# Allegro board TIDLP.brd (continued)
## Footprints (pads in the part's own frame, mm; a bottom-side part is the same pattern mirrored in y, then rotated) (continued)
CAP-FK-V-CASEE_PAN
  rect 1.422x4.166 smd: 1(0,-2.857) 2(0,2.857)
CAP_0402
  rect 0.508x0.508 smd: 1(-0.521,0) 2(0.521,0)
CAP_0603
  rect 1.067x1.016 smd: 1(-0.864,0) 2(0.864,0)
CAP_0805
  rect 1.27x1.524 smd: 1(-0.965,0) 2(0.965,0)
CAP_1206
  rect 1.575x1.626 smd: 1(-1.714,0) 2(1.714,0)
CAP_1210
  rect 1.575x2.591 smd: 1(-1.397,0) 2(1.397,0)
CN3_53398_MOLEX
  rect 2.108x2.997 smd: (-3.8,-1.85) (3.8,-1.85)
  rect 0.61x1.6 smd: 1(-1.25,1.063) 2(0,1.063) 3(1.25,1.063)
CN120_QTH_SAMTEC
  round 0.762 hole 1.016 unplated: (-19.24,2.03) (19.24,2.03)
  rect 0.305x1.448 smd: 1(-17.25,3.08) 2(-17.25,-3.09) 3(-16.75,3.08) 4(-16.75,-3.09) 5(-16.25,3.08) 6(-16.25,-3.09) 7(-15.75,3.08) 8(-15.75,-3.09) 9(-15.25,3.08) 10(-15.25,-3.09) 11(-14.75,3.08) 12(-14.75,-3.09) 13(-14.25,3.08) 14(-14.25,-3.09) 15(-13.75,3.08) 16(-13.75,-3.09) 17(-13.25,3.08) 18(-13.25,-3.09) 19(-12.75,3.08) 20(-12.75,-3.09) 21(-12.25,3.08) 22(-12.25,-3.09) 23(-11.75,3.08) 24(-11.75,-3.09) 25(-11.25,3.08) 26(-11.25,-3.09) 27(-10.75,3.08) 28(-10.75,-3.09) 29(-10.25,3.08) 30(-10.25,-3.09) 31(-9.75,3.08) 32(-9.75,-3.09) 33(-9.25,3.08) 34(-9.25,-3.09) 35(-8.75,3.08) 36(-8.75,-3.09) 37(-8.25,3.08) 38(-8.25,-3.09) 39(-7.75,3.08) 40(-7.75,-3.09) 41(-7.25,3.08) 42(-7.25,-3.09) 43(-6.75,3.08) 44(-6.75,-3.09) 45(-6.25,3.08) 46(-6.25,-3.09) 47(-5.75,3.08) 48(-5.75,-3.09) 49(-5.25,3.08) 50(-5.25,-3.09) 51(-4.75,3.08) 52(-4.75,-3.09) 53(-4.25,3.08) 54(-4.25,-3.09) 55(-3.75,3.08) 56(-3.75,-3.09) 57(-3.25,3.08) 58(-3.25,-3.09) 59(-2.75,3.08) 60(-2.75,-3.09) 61(2.75,3.08) 62(2.75,-3.09) 63(3.25,3.08) 64(3.25,-3.09) 65(3.75,3.08) 66(3.75,-3.09) 67(4.25,3.08) 68(4.25,-3.09) 69(4.75,3.08) 70(4.75,-3.09) 71(5.25,3.08) 72(5.25,-3.09) 73(5.75,3.08) 74(5.75,-3.09) 75(6.25,3.08) 76(6.25,-3.09) 77(6.75,3.08) 78(6.75,-3.09) 79(7.25,3.08) 80(7.25,-3.09) 81(7.75,3.08) 82(7.75,-3.09) 83(8.25,3.08) 84(8.25,-3.09) 85(8.75,3.08) 86(8.75,-3.09) 87(9.25,3.08) 88(9.25,-3.09) 89(9.75,3.08) 90(9.75,-3.09) 91(10.25,3.08) 92(10.25,-3.09) 93(10.75,3.08) 94(10.75,-3.09) 95(11.25,3.08) 96(11.25,-3.09) 97(11.75,3.08) 98(11.75,-3.09) 99(12.25,3.08) 100(12.25,-3.09) 101(12.75,3.08) 102(12.75,-3.09) 103(13.25,3.08) 104(13.25,-3.09) 105(13.75,3.08) 106(13.75,-3.09) 107(14.25,3.08) 108(14.25,-3.09) 109(14.75,3.08) 110(14.75,-3.09) 111(15.25,3.08) 112(15.25,-3.09) 113(15.75,3.08) 114(15.75,-3.09) 115(16.25,3.08) 116(16.25,-3.09) 117(16.75,3.08) 118(16.75,-3.09) 119(17.25,3.08) 120(17.25,-3.09)
  rect 2.54x0.635 smd: G1(-18.445,0) G4(-1.555,0) G5(1.555,0) G8(18.445,0)
  rect 4.699x0.635 smd: G2(-13.175,0) G3(-6.825,0) G6(6.825,0) G7(13.175,0)
CN150CUSTOM_REV
  round 1.27 hole 1.676 unplated: (-6.096,-1.397) (36.576,-1.397)
  round 1.27 hole 4.623 unplated: (-3.81,3.175) (34.29,3.175)
  round 0.762 smd: 1A(0,0) 1B(0,1.27) 1C(0,2.54) 1D(0,3.81) 1E(0,5.08) 1F(0,6.35) 2A(1.27,0) 2B(1.27,1.27) 2C(1.27,2.54) 2D(1.27,3.81) 2E(1.27,5.08) 2F(1.27,6.35) 3A(2.54,0) 3B(2.54,1.27) 3C(2.54,2.54) 3D(2.54,3.81) 3E(2.54,5.08) 3F(2.54,6.35) 4A(3.81,0) 4B(3.81,1.27) 4C(3.81,2.54) 4D(3.81,3.81) 4E(3.81,5.08) 4F(3.81,6.35) 5A(5.08,0) 5B(5.08,1.27) 5C(5.08,2.54) 5D(5.08,3.81) 5E(5.08,5.08) 5F(5.08,6.35) 6A(6.35,0) 6B(6.35,1.27) 6C(6.35,2.54) 6D(6.35,3.81) 6E(6.35,5.08) 6F(6.35,6.35) 7A(7.62,0) 7B(7.62,1.27) 7C(7.62,2.54) 7D(7.62,3.81) 7E(7.62,5.08) 7F(7.62,6.35) 8A(8.89,0) 8B(8.89,1.27) 8C(8.89,2.54) 8D(8.89,3.81) 8E(8.89,5.08) 8F(8.89,6.35) 9A(10.16,0) 9B(10.16,1.27) 9C(10.16,2.54) 9D(10.16,3.81) 9E(10.16,5.08) 9F(10.16,6.35) 10A(11.43,0) 10B(11.43,1.27) 10C(11.43,2.54) 10D(11.43,3.81) 10E(11.43,5.08) 10F(11.43,6.35) 11A(12.7,0) 11B(12.7,1.27) 11C(12.7,2.54) 11D(12.7,3.81) 11E(12.7,5.08) 11F(12.7,6.35) 12A(13.97,0) 12B(13.97,1.27) 12C(13.97,2.54) 12D(13.97,3.81) 12E(13.97,5.08) 12F(13.97,6.35) 13A(15.24,0) 13B(15.24,1.27) 13C(15.24,2.54) 13D(15.24,3.81) 13E(15.24,5.08) 13F(15.24,6.35) 14A(16.51,0) 14B(16.51,1.27) 14C(16.51,2.54) 14D(16.51,3.81) 14E(16.51,5.08) 14F(16.51,6.35) 15A(17.78,0) 15B(17.78,1.27) 15C(17.78,2.54) 15D(17.78,3.81) 15E(17.78,5.08) 15F(17.78,6.35) 16A(19.05,0) 16B(19.05,1.27) 16C(19.05,2.54) 16D(19.05,3.81) 16E(19.05,5.08) 16F(19.05,6.35) 17A(20.32,0) 17B(20.32,1.27) 17C(20.32,2.54) 17D(20.32,3.81) 17E(20.32,5.08) 17F(20.32,6.35) 18A(21.59,0) 18B(21.59,1.27) 18C(21.59,2.54) 18D(21.59,3.81) 18E(21.59,5.08) 18F(21.59,6.35) 19A(22.86,0) 19B(22.86,1.27) 19C(22.86,2.54) 19D(22.86,3.81) 19E(22.86,5.08) 19F(22.86,6.35) 20A(24.13,0) 20B(24.13,1.27) 20C(24.13,2.54) 20D(24.13,3.81) 20E(24.13,5.08) 20F(24.13,6.35) 21A(25.4,0) 21B(25.4,1.27) 21C(25.4,2.54) 21D(25.4,3.81) 21E(25.4,5.08) 21F(25.4,6.35) 22A(26.67,0) 22B(26.67,1.27) 22C(26.67,2.54) 22D(26.67,3.81) 22E(26.67,5.08) 22F(26.67,6.35) 23A(27.94,0) 23B(27.94,1.27) 23C(27.94,2.54) 23D(27.94,3.81) 23E(27.94,5.08) 23F(27.94,6.35) 24A(29.21,0) 24B(29.21,1.27) 24C(29.21,2.54) 24D(29.21,3.81) 24E(29.21,5.08) 24F(29.21,6.35) 25A(30.48,0) 25B(30.48,1.27) 25C(30.48,2.54) 25D(30.48,3.81) 25E(30.48,5.08) 25F(30.48,6.35)
CONN4-52808_MOLEX
  rect 0.61x1.448 smd: 1(-1.501,-1.778) 3(0.5,-1.778)
  rect 0.61x1.651 smd: 2(-0.5,1.778) 4(1.501,1.778)
CONN4-53398_MOLEX
  rect 0.61x1.6 smd: 1(-1.875,0) 2(-0.625,0) 3(0.625,0) 4(1.875,0)
  rect 2.108x2.997 smd: 5(-4.425,-2.913) 6(4.425,-2.913)
CONN4-67068-1000_MOLEX
  round 1.422 hole 0.914: 1(0,0) 2(-2.5,0) 3(-2.5,-2) 4(0,-2)
  round 3.175 hole 2.286: S1(-7.27,-4.71) S2(4.77,-4.71)
CONN5-53398-0590_MOLEX
  rect 0.61x1.6 smd: 1(-2.5,1.063) 2(-1.25,1.063) 3(0,1.063) 4(1.25,1.063) 5(2.5,1.063)
  rect 2.108x2.997 smd: 6(-5.05,-1.85) 7(5.05,-1.85)
CONN6-53398-0690_MOLEX
  rect 0.61x1.6 smd: 1(-3.125,1.063) 2(-1.875,1.063) 3(-0.625,1.063) 4(0.625,1.063) 5(1.875,1.063) 6(3.125,1.063)
  rect 2.108x2.997 smd: 7(-5.675,-1.85) 8(5.675,-1.85)
CONN8-43045-0813_MOLEX
  round 1.524 hole 1.016: (-11.989,3.937) (2.997,3.937) 1(0,0) 2(-2.997,0) 3(-5.994,0) 4(-8.992,0) 5(0,2.997) 6(-2.997,2.997) 7(-5.994,2.997) 8(-8.992,2.997)
CONN10-SQT_SAM
  rect 1.778x1.778 hole 1.27: 1(0,0)
  round 1.778 hole 1.27: 2(0,-1.999) 3(0,-3.998) 4(0,-5.997) 5(0,-7.996) 6(0,-9.995) 7(0,-11.994) 8(0,-13.993) 9(0,-15.992) 10(0,-17.991)
CONN12-53398_MOLEX
  rect 2.108x2.997 smd: (-9.425,-1.85) (9.425,-1.85)
  rect 0.61x1.6 smd: 1(-6.875,1.063) 2(-5.625,1.063) 3(-4.375,1.063) 4(-3.125,1.063) 5(-1.875,1.063) 6(-0.625,1.063) 7(0.625,1.063) 8(1.875,1.063) 9(3.125,1.063) 10(4.375,1.063) 11(5.625,1.063) 12(6.875,1.063)
CONN12-FH12_HRS
  rect 1.854x2.184 smd: (-4.5,-2.895) (4.5,-2.895)
  rect 0.254x1.016 smd: 1(-2.75,0) 2(-2.25,0) 3(-1.75,0) 4(-1.25,0) 5(-0.75,0) 6(-0.25,0) 7(0.25,0) 8(0.75,0) 9(1.25,0) 10(1.75,0) 11(2.25,0) 12(2.75,0)
CONN12-SMT-TSM-112-SV_SAMTEC
  rect 3.175x1.27 smd: 1(-1.587,-13.97) 2(1.587,-11.43) 3(-1.587,-8.89) 4(1.587,-6.35) 5(-1.587,-3.81) 6(1.587,-1.27) 7(-1.587,1.27) 8(1.587,3.81) 9(-1.587,6.35) 10(1.587,8.89) 11(-1.587,11.43) 12(1.587,13.97)
CONN14-53048_MLX
  rect 1.016x1.016 hole 0.508: 1(0,0)
  round 1.016 hole 0.508: 2(0,-1.25) 3(0,-2.5) 4(0,-3.75) 5(0,-5) 6(0,-6.25) 7(0,-7.5) 8(0,-8.75) 9(0,-10) 10(0,-11.25) 11(0,-12.5) 12(0,-13.75) 13(0,-15) 14(0,-16.25)
CONN14-XF2M_OMRON
  rect 0.254x1.295 smd: 1(3.25,0) 2(2.75,0) 3(2.25,0) 4(1.75,0) 5(1.25,0) 6(0.75,0) 7(0.25,0) 8(-0.25,0) 9(-0.75,0) 10(-1.25,0) 11(-1.75,0) 12(-2.25,0) 13(-2.75,0) 14(-3.25,0)
  rect 1.905x1.524 smd: 15(-5.201,-3.987) 16(5.201,-3.987)
CONN20-TSM-110-0X-X-DV-A_SAMTEC
  round 1.016 hole 1.88 unplated: (-10.16,0) (10.16,0)
  rect 1.27x3.175 smd: 1(-11.43,-2.731) 2(-11.43,2.731) 3(-8.89,-2.731) 4(-8.89,2.731) 5(-6.35,-2.731) 6(-6.35,2.731) 7(-3.81,-2.731) 8(-3.81,2.731) 9(-1.27,-2.731) 10(-1.27,2.731) 11(1.27,-2.731) 12(1.27,2.731) 13(3.81,-2.731) 14(3.81,2.731) 15(6.35,-2.731) 16(6.35,2.731) 17(8.89,-2.731) 18(8.89,2.731) 19(11.43,-2.731) 20(11.43,2.731)
CONN22-B22B-PHD_JST
  rect 1.473x1.473 hole 0.965: 1(0,0)
  round 1.473 hole 0.965: 2(2,0) 3(0,2) 4(2,2) 5(0,4) 6(2,4) 7(0,6) 8(2,6) 9(0,8) 10(2,8) 11(0,10) 12(2,10) 13(0,12) 14(2,12) 15(0,14) 16(2,14) 17(0,16) 18(2,16) 19(0,18) 20(2,18) 21(0,20) 22(2,20)
CRY4-P73_ECS
  rect 1.397x2.007 smd: 1(-2.54,-2.095) 2(2.54,-2.095) 3(2.54,2.095) 4(-2.54,2.095)
DIO-SMA
  rect 2.489x1.702 smd: 1(-2.007,0) 2(2.007,0)
DIO-SMB
  rect 2.4x2.4 smd: 1(-2.2,0) 2(2.2,0)
DIO_SMA
  rect 2.489x1.702 smd: 1(-2.007,0) 2(2.007,0)
FLTR_0603
  rect 1.067x1.016 smd: 1(-0.864,0) 2(0.864,0)
HDR1X3-TMM1030X-X-S_SAM
  rect 1.524x1.524 hole 1.016: 1(0,0)
  round 1.524 hole 1.016: 2(2,0) 3(4,0)
HDR2_2MM
  rect 1.651x1.651 hole 1.143: 1(0,0)
  round 1.651 hole 1.143: 2(2,0)
HDR10X2-5103308_TYCO
  round 1.651 hole 1.067: 1(0,0) 2(2.54,0) 3(0,-2.54) 4(2.54,-2.54) 5(0,-5.08) 6(2.54,-5.08) 7(0,-7.62) 8(2.54,-7.62) 9(0,-10.16) 10(2.54,-10.16) 11(0,-12.7) 12(2.54,-12.7) 13(0,-15.24) 14(2.54,-15.24) 15(0,-17.78) 16(2.54,-17.78) 17(0,-20.32) 18(2.54,-20.32) 19(0,-22.86) 20(2.54,-22.86)
HDR14-87227_AMP
  rect 1.473x1.473 hole 0.965: 1(0,0)
  round 1.473 hole 0.965: 2(0,2.54) 3(2.54,0) 4(2.54,2.54) 5(5.08,0) 6(5.08,2.54) 7(7.62,0) 8(7.62,2.54) 9(10.16,0) 10(10.16,2.54) 11(12.7,0) 12(12.7,2.54) 13(15.24,0) 14(15.24,2.54)
IND2-SPR7030_BOU
  rect 2.413x2.489 smd: 1(-3.054,0) 2(3.054,0)
IND_0805
  rect 1.27x1.524 smd: 1(-0.965,0) 2(0.965,0)
IND_SERH
  rect 1.702x3.81 smd: 1(-2.85,0) 2(2.85,0)
IND_SRR1005
  rect 2.997x2.794 smd: 1(5.144,0) 2(-5.144,0)
JACK3-DCPOWER_CUI_MOD
  round 1.524 hole 1.016: (0,1.25) (0,1) (0,0.75) (0,0.5) (0,0.25) (0,-0.25) (0,-0.5) (0,-0.75) (0,-1) (0,-1.25) (2,4.7) (2.25,4.7) (2.5,4.7) (2.75,4.7) (3.25,4.7) (3.5,4.7) (3.75,4.7) (4,4.7) (6,1) (6,0.75) (6,0.5) (6,0.25) (6,-0.25) (6,-0.5) (6,-0.75) (6,-1) GND1(3,4.7) GND2(6,0) P12V_IN(0,0)
KYCON-CN9SMTA
  round 3.81 hole 3.048: (-12.495,-0.325) (12.495,-0.325)
  round 0.762 hole 1.524 unplated: (-8.99,-0.325) (8.99,-0.325)
  rect 0.8x3.7 smd: 1(-5.54,0.325) 2(-2.77,0.325) 3(0,0.325) 4(2.77,0.325) 5(5.54,0.325) 6(-4.155,0.325) 7(-1.385,0.325) 8(1.385,0.325) 9(4.155,0.325)
LCC8-MXD2125_MEMSIC
  round 0.508 smd: (0,0.648)
  rect 2.032x0.864 smd: 1(-2.235,1.27) 2(-2.235,0) 3(-2.235,-1.27) 5(2.235,-1.27) 6(2.235,0) 7(2.235,1.27)
  rect 0.864x2.032 smd: 4(0,-2.235) 8(0,2.235)
LED_S_TYPE
  rect 0.787x1.092 smd: 1(-1.25,0.65)
  rect 0.787x0.889 smd: 2(1.25,0.65) 3(-1.25,-0.65) 4(1.25,-0.65)
MH276-157GND
  round 7.01 hole 3.988: 1(0,0)
  round 0.813 hole 0.406: 2(0,3.048) 3(-2.159,2.159) 4(-3.048,0) 5(-2.159,-2.159) 6(0,-3.048) 7(2.159,-2.159) 8(3.048,0) 9(2.159,2.159)
MICTOR_HPA
  round 1.27 hole 2.388 unplated: (11.43,0)
  rect 0.432x1.27 smd: 1(5.715,3.531) 2(5.715,-3.531) 3(5.08,3.531) 4(5.08,-3.531) 5(4.445,3.531) 6(4.445,-3.531) 7(3.81,3.531) 8(3.81,-3.531) 9(3.175,3.531) 10(3.175,-3.531) 11(2.54,3.531) 12(2.54,-3.531) 13(1.905,3.531) 14(1.905,-3.531) 15(1.27,3.531) 16(1.27,-3.531) 17(0.635,3.531) 18(0.635,-3.531) 19(0,3.531) 20(0,-3.531) 21(-0.635,3.531) 22(-0.635,-3.531) 23(-1.27,3.531) 24(-1.27,-3.531) 25(-1.905,3.531) 26(-1.905,-3.531) 27(-2.54,3.531) 28(-2.54,-3.531) 29(-3.175,3.531) 30(-3.175,-3.531) 31(-3.81,3.531) 32(-3.81,-3.531) 33(-4.445,3.531) 34(-4.445,-3.531) 35(-5.08,3.531) 36(-5.08,-3.531) 37(-5.715,3.531) 38(-5.715,-3.531)
  round 1.397 hole 0.889: G1(-5.08,0) G2(-2.54,0) G3(0,0) G4(2.54,0) G5(5.08,0)
POT-3314G
  rect 1.321x1.321 smd: 1(-1.156,2.756) 3(1.156,2.756)
  rect 1.981x1.321 smd: 2(0,-2.756)
PQFP24-QFN_SI
  oval 1.016x0.305 smd: 1(-2,1.25) 6(-2,-1.25) 13(2,-1.25) 18(2,1.25)
  rect 1.016x0.305 smd: 2(-2,0.75) 3(-2,0.25) 4(-2,-0.25) 5(-2,-0.75) 14(2,-0.75) 15(2,-0.25) 16(2,0.25) 17(2,0.75)
  oval 0.305x1.016 smd: 7(-1.25,-2) 12(1.25,-2) 19(1.25,2) 24(-1.25,2)
  rect 0.305x1.016 smd: 8(-0.75,-2) 9(-0.25,-2) 10(0.25,-2) 11(0.75,-2) 20(0.75,2) 21(0.25,2) 22(-0.25,2) 23(-0.75,2)
  round 0.61 hole 0.305: 25(0,0) PAD(-0.889,0.889)
PQFP100-PZ_TI
  rect 1.524x0.254 smd: 1(-7.762,6) 2(-7.762,5.5) 3(-7.762,5) 4(-7.762,4.5) 5(-7.762,4) 6(-7.762,3.5) 7(-7.762,3) 8(-7.762,2.5) 9(-7.762,2) 10(-7.762,1.5) 11(-7.762,1) 12(-7.762,0.5) 13(-7.762,0) 14(-7.762,-0.5) 15(-7.762,-1) 16(-7.762,-1.5) 17(-7.762,-2) 18(-7.762,-2.5) 19(-7.762,-3) 20(-7.762,-3.5) 21(-7.762,-4) 22(-7.762,-4.5) 23(-7.762,-5) 24(-7.762,-5.5) 25(-7.762,-6) 51(7.762,-6) 52(7.762,-5.5) 53(7.762,-5) 54(7.762,-4.5) 55(7.762,-4) 56(7.762,-3.5) 57(7.762,-3) 58(7.762,-2.5) 59(7.762,-2) 60(7.762,-1.5) 61(7.762,-1) 62(7.762,-0.5) 63(7.762,0) 64(7.762,0.5) 65(7.762,1) 66(7.762,1.5) 67(7.762,2) 68(7.762,2.5) 69(7.762,3) 70(7.762,3.5) 71(7.762,4) 72(7.762,4.5) 73(7.762,5) 74(7.762,5.5) 75(7.762,6)
  rect 0.254x1.524 smd: 26(-6,-7.762) 27(-5.5,-7.762) 28(-5,-7.762) 29(-4.5,-7.762) 30(-4,-7.762) 31(-3.5,-7.762) 32(-3,-7.762) 33(-2.5,-7.762) 34(-2,-7.762) 35(-1.5,-7.762) 36(-1,-7.762) 37(-0.5,-7.762) 38(0,-7.762) 39(0.5,-7.762) 40(1,-7.762) 41(1.5,-7.762) 42(2,-7.762) 43(2.5,-7.762) 44(3,-7.762) 45(3.5,-7.762) 46(4,-7.762) 47(4.5,-7.762) 48(5,-7.762) 49(5.5,-7.762) 50(6,-7.762) 76(6,7.762) 77(5.5,7.762) 78(5,7.762) 79(4.5,7.762) 80(4,7.762) 81(3.5,7.762) 82(3,7.762) 83(2.5,7.762) 84(2,7.762) 85(1.5,7.762) 86(1,7.762) 87(0.5,7.762) 88(0,7.762) 89(-0.5,7.762) 90(-1,7.762) 91(-1.5,7.762) 92(-2,7.762) 93(-2.5,7.762) 94(-3,7.762) 95(-3.5,7.762) 96(-4,7.762) 97(-4.5,7.762) 98(-5,7.762) 99(-5.5,7.762) 100(-6,7.762)
QF48_PPAD
  rect 1.524x0.254 smd: 1(-4.445,2.752) 2(-4.445,2.252) 3(-4.445,1.751) 4(-4.445,1.251) 5(-4.445,0.751) 6(-4.445,0.25) 7(-4.445,-0.25) 8(-4.445,-0.751) 9(-4.445,-1.251) 10(-4.445,-1.751) 11(-4.445,-2.252) 12(-4.445,-2.752) 25(4.445,-2.752) 26(4.445,-2.252) 27(4.445,-1.751) 28(4.445,-1.251) 29(4.445,-0.751) 30(4.445,-0.25) 31(4.445,0.25) 32(4.445,0.751) 33(4.445,1.251) 34(4.445,1.751) 35(4.445,2.252) 36(4.445,2.752)
  rect 0.254x1.524 smd: 13(-2.752,-4.445) 14(-2.252,-4.445) 15(-1.751,-4.445) 16(-1.251,-4.445) 17(-0.751,-4.445) 18(-0.25,-4.445) 19(0.25,-4.445) 20(0.751,-4.445) 21(1.251,-4.445) 22(1.751,-4.445) 23(2.252,-4.445) 24(2.752,-4.445) 37(2.752,4.445) 38(2.252,4.445) 39(1.751,4.445) 40(1.251,4.445) 41(0.751,4.445) 42(0.25,4.445) 43(-0.25,4.445) 44(-0.751,4.445) 45(-1.251,4.445) 46(-1.751,4.445) 47(-2.252,4.445) 48(-2.752,4.445)
RES_0402
  rect 0.508x0.508 smd: 1(-0.521,0) 2(0.521,0)
RES_0603
  rect 1.067x1.016 smd: 1(-0.864,0) 2(0.864,0)
RES_0805
  rect 1.27x1.524 smd: 1(-0.965,0) 2(0.965,0)
RES_1206
  rect 1.575x1.626 smd: 1(-1.714,0) 2(1.714,0)
RES_1210
  rect 1.575x2.591 smd: 1(-1.397,0) 2(1.397,0)
RES_2010
  rect 1.778x2.591 smd: 1(-2.21,0) 2(2.21,0)
RNET8-EXB38V_PAN
  rect 0.94x0.787 smd: 1(-0.8,1.314) 4(-0.8,-1.314) 5(0.8,-1.314) 8(0.8,1.314)
  rect 0.94x0.559 smd: 2(-0.8,0.4) 3(-0.8,-0.4) 6(0.8,-0.4) 7(0.8,0.4)
RNET16-EXB-2HV_PAN
  rect 0.686x0.305 smd: 1(-0.851,1.75) 2(-0.851,1.25) 3(-0.851,0.75) 4(-0.851,0.25) 5(-0.851,-0.25) 6(-0.851,-0.75) 7(-0.851,-1.25) 8(-0.851,-1.75) 9(0.851,-1.75) 10(0.851,-1.25) 11(0.851,-0.75) 12(0.851,-0.25) 13(0.851,0.25) 14(0.851,0.75) 15(0.851,1.25) 16(0.851,1.75)
SM_TO_252_DPAK
  rect 1.6x2.997 smd: 1(-2.286,-4.318) 2(0,-4.318) 3(2.286,-4.318)
  rect 6.198x5.791 smd: 4(0,2.642)
SMC_ST
  rect 2.794x3.81 smd: 1(-3.569,0) 2(3.569,0)
SMD_49
  rect 5.486x2.007 smd: 1(-4.75,0) 2(4.75,0)
SOD-123
  rect 1.016x1.27 smd: 1(-1.778,0) 2(1.778,0)
SOIC5-DBV_TI
  rect 1.321x0.61 smd: 1(-1.187,0.95) 2(-1.187,0) 3(-1.187,-0.95) 4(1.187,-0.95) 5(1.187,0.95)
SOIC6-DBV_TI
  rect 1.321x0.61 smd: 1(-1.187,0.95) 2(-1.187,0) 3(-1.187,-0.95) 4(1.187,-0.95) 5(1.187,0) 6(1.187,0.95)
SOIC6-DRL_TI
  rect 0.356x1.067 smd: 1(-0.5,-0.828) 2(0,-0.828) 3(0.5,-0.828) 4(0.5,0.828) 5(0,0.828) 6(-0.5,0.828)
SOIC8-D_TI
  rect 0.635x2.032 smd: 1(-1.905,-2.489) 2(-0.635,-2.489) 3(0.635,-2.489) 4(1.905,-2.489) 5(1.905,2.489) 6(0.635,2.489) 7(-0.635,2.489) 8(-1.905,2.489)
SOIC8-PW_TI
  rect 0.356x1.524 smd: 1(-0.975,-2.96) 2(-0.325,-2.96) 3(0.325,-2.96) 4(0.975,-2.96) 5(0.975,2.96) 6(0.325,2.96) 7(-0.325,2.96) 8(-0.975,2.96)
SOIC14-PW_TI
  rect 0.305x1.778 smd: 1(-1.951,-2.794) 2(-1.301,-2.794) 3(-0.65,-2.794) 4(0,-2.794) 5(0.65,-2.794) 6(1.301,-2.794) 7(1.951,-2.794) 8(1.951,2.794) 9(1.301,2.794) 10(0.65,2.794) 11(0,2.794) 12(-0.65,2.794) 13(-1.301,2.794) 14(-1.951,2.794)
SOIC16-PW_TI
  rect 0.356x1.524 smd: 1(-2.275,-2.96) 2(-1.625,-2.96) 3(-0.975,-2.96) 4(-0.325,-2.96) 5(0.325,-2.96) 6(0.975,-2.96) 7(1.625,-2.96) 8(2.275,-2.96) 9(2.275,2.96) 10(1.625,2.96) 11(0.975,2.96) 12(0.325,2.96) 13(-0.325,2.96) 14(-0.975,2.96) 15(-1.625,2.96) 16(-2.275,2.96)
SOIC24-PW_TI
  rect 0.356x1.524 smd: 1(-3.575,-2.96) 2(-2.925,-2.96) 3(-2.275,-2.96) 4(-1.625,-2.96) 5(-0.975,-2.96) 6(-0.325,-2.96) 7(0.325,-2.96) 8(0.975,-2.96) 9(1.625,-2.96) 10(2.275,-2.96) 11(2.925,-2.96) 12(3.575,-2.96) 13(3.575,2.96) 14(2.925,2.96) 15(2.275,2.96) 16(1.625,2.96) 17(0.975,2.96) 18(0.325,2.96) 19(-0.325,2.96) 20(-0.975,2.96) 21(-1.625,2.96) 22(-2.275,2.96) 23(-2.925,2.96) 24(-3.575,2.96)
SOIC56-DGG_TI
  rect 0.305x1.524 smd: 1(-6.75,-3.775) 2(-6.25,-3.775) 3(-5.75,-3.775) 4(-5.25,-3.775) 5(-4.75,-3.775) 6(-4.25,-3.775) 7(-3.75,-3.775) 8(-3.25,-3.775) 9(-2.75,-3.775) 10(-2.25,-3.775) 11(-1.75,-3.775) 12(-1.25,-3.775) 13(-0.75,-3.775) 14(-0.25,-3.775) 15(0.25,-3.775) 16(0.75,-3.775) 17(1.25,-3.775) 18(1.75,-3.775) 19(2.25,-3.775) 20(2.75,-3.775) 21(3.25,-3.775) 22(3.75,-3.775) 23(4.25,-3.775) 24(4.75,-3.775) 25(5.25,-3.775) 26(5.75,-3.775) 27(6.25,-3.775) 28(6.75,-3.775) 29(6.75,3.775) 30(6.25,3.775) 31(5.75,3.775) 32(5.25,3.775) 33(4.75,3.775) 34(4.25,3.775) 35(3.75,3.775) 36(3.25,3.775) 37(2.75,3.775) 38(2.25,3.775) 39(1.75,3.775) 40(1.25,3.775) 41(0.75,3.775) 42(0.25,3.775) 43(-0.25,3.775) 44(-0.75,3.775) 45(-1.25,3.775) 46(-1.75,3.775) 47(-2.25,3.775) 48(-2.75,3.775) 49(-3.25,3.775) 50(-3.75,3.775) 51(-4.25,3.775) 52(-4.75,3.775) 53(-5.25,3.775) 54(-5.75,3.775) 55(-6.25,3.775) 56(-6.75,3.775)
SOT23-3_FC
  rect 1.016x1.372 smd: 1(0.94,1.092) 2(-0.94,1.092) 3(0,-1.092)
SOT23-DBV_TI
  rect 0.508x1.372 smd: 1(-0.94,-1.219) 2(0,-1.219) 3(0.94,-1.219) 4(0.94,1.219) 5(-0.94,1.219)
SOT23AVXC
  rect 1.016x1.372 smd: 1(0,-1.092) 2(-0.94,1.092) 3(0.94,1.092)
SOT23AVXD
  rect 1.016x1.372 smd: 1(-0.94,1.092) 2(0.94,1.092) 3(0,-1.092)
SOT223
  rect 1.499x2.007 smd: 1(-2.299,-3.15) 2(0,-3.15) 3(2.299,-3.15)
  rect 3.81x2.007 smd: 4(0,3.15)
SOT_323
  rect 0.762x1.067 smd: 1(0.66,0.94) 2(-0.66,0.94) 3(0,-0.94)
SSOP_8
  rect 0.305x1.6 smd: 1(-0.975,-2.235) 2(-0.325,-2.235) 3(0.325,-2.235) 4(0.975,-2.235) 5(0.975,2.136) 6(0.325,2.136) 7(-0.325,2.136) 8(-0.975,2.136)
SW_GT12
  rect 3.175x0.762 smd: (-2.603,2.54) (-2.603,-2.54) (2.603,0) 1(2.603,2.54) 3(2.603,-2.54)
TP
  round 1.219 hole 0.711: 1(0,0)
TSOP_56_48_DUAL_SKT
  round 1.27 hole 1.27 unplated: (-5.08,4.743) (5.08,4.743)
  rect 1.778x0.305 smd: 1(-9.69,6.75) 2(-9.69,6.25) 3(-9.69,5.75) 4(-9.69,5.25) 5(-9.69,4.75) 6(-9.69,4.25) 7(-9.69,3.75) 8(-9.69,3.25) 9(-9.69,2.75) 10(-9.69,2.25) 11(-9.69,1.75) 12(-9.69,1.25) 13(-9.69,0.75) 14(-9.69,0.25) 15(-9.69,-0.25) 16(-9.69,-0.75) 17(-9.69,-1.25) 18(-9.69,-1.75) 19(-9.69,-2.25) 20(-9.69,-2.75) 21(-9.69,-3.25) 22(-9.69,-3.75) 23(-9.69,-4.25) 24(-9.69,-4.75) 25(-9.69,-5.25) 26(-9.69,-5.75) 27(-9.69,-6.25) 28(-9.69,-6.75) 29(9.69,-6.75) 30(9.69,-6.25) 31(9.69,-5.75) 32(9.69,-5.25) 33(9.69,-4.75) 34(9.69,-4.25) 35(9.69,-3.75) 36(9.69,-3.25) 37(9.69,-2.75) 38(9.69,-2.25) 39(9.69,-1.75) 40(9.69,-1.25) 41(9.69,-0.75) 42(9.69,-0.25) 43(9.69,0.25) 44(9.69,0.75) 45(9.69,1.25) 46(9.69,1.75) 47(9.69,2.25) 48(9.69,2.75) 49(9.69,3.25) 50(9.69,3.75) 51(9.69,4.25) 52(9.69,4.75) 53(9.69,5.25) 54(9.69,5.75) 55(9.69,6.25) 56(9.69,6.75)
TSOPII_44
  rect 0.61x1.143 smd: 1(-8.4,-6) 2(-7.6,-6) 3(-6.8,-6) 4(-6,-6) 5(-5.2,-6) 6(-4.4,-6) 7(-3.6,-6) 8(-2.8,-6) 9(-2,-6) 10(-1.2,-6) 11(-0.4,-6) 12(0.4,-6) 13(1.2,-6) 14(2,-6) 15(2.8,-6) 16(3.6,-6) 17(4.4,-6) 18(5.2,-6) 19(6,-6) 20(6.8,-6) 21(7.6,-6) 22(8.4,-6) 23(8.4,6) 24(7.6,6) 25(6.8,6) 26(6,6) 27(5.2,6) 28(4.4,6) 29(3.6,6) 30(2.8,6) 31(2,6) 32(1.2,6) 33(0.4,6) 34(-0.4,6) 35(-1.2,6) 36(-2,6) 37(-2.8,6) 38(-3.6,6) 39(-4.4,6) 40(-5.2,6) 41(-6,6) 42(-6.8,6) 43(-7.6,6) 44(-8.4,6)
TSSOP_8
  rect 0.406x1.803 smd: 1(-0.975,-2.954) 2(-0.325,-2.954) 3(0.325,-2.954) 4(0.975,-2.954) 5(0.975,2.954) 6(0.325,2.954) 7(-0.325,2.954) 8(-0.975,2.954)
TSSOP_14
  rect 0.305x1.778 smd: 1(-1.951,-2.794) 2(-1.301,-2.794) 3(-0.65,-2.794) 4(0,-2.794) 5(0.65,-2.794) 6(1.301,-2.794) 7(1.951,-2.794) 8(1.951,2.794) 9(1.301,2.794) 10(0.65,2.794) 11(0,2.794) 12(-0.65,2.794) 13(-1.301,2.794) 14(-1.951,2.794)
unnamed#2
  round 0.762 smd: 1(0,0)
unnamed#3
  round 2.362 hole 2.349 unplated: (-20.955,20.955) (-20.955,-20.955) (20.955,20.955) (20.955,-20.955)
  round 0.635 hole 0.66 unplated: (-18.989,-18.989) (18.989,18.989)
VISHAY_IR_TSOP348
  rect 1.575x1.575 hole 1.067: 1(0,0)
  round 1.575 hole 1.067: 2(2.54,0) 3(5.08,0)

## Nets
AGND: C539.2 C558.2 C559.2 C560.2 C561.2 C562.2 C563.2 C564.2 C565.2 C573.2 C574.2 C575.2 J11.2 J11.5 R571.2 R572.2 R583.2 R585.2 R586.1 R598.2 U7.13 U7.14 U7.25 U7.39
GND: C1.1 C2.2 C3.2 C4.2 C5.2 C7.2 C8.2 C9.2 C10.2 C11.2 C12.2 C13.2 C14.2 C15.2 C16.2 C17.1 C18.2 C19.2 C20.2 C21.2 C22.1 C23.1 C25.1 C26.1 C27.1 C28.1 C29.1 C30.1 C31.1 C33.1 C34.1 C35.1 C36.1 C37.1 C503.1 C504.1 C506.1 C508.1 C509.1 C511.1 C512.1 C513.2 C514.2 C516.1 C517.1 C518.1 C519.1 C520.1 C521.2 C522.2 C523.1 C524.2 C525.2 C526.1 C527.1 C529.1 C530.2 C531.2 C532.2 C533.2 C534.2 C535.2 C536.2 C537.2 C538.2 C540.2 C541.1 C543.2 C544.2 C545.1 C546.2 C547.2 C548.2 C549.2 C550.2 C551.1 C552.2 C553.2 C554.2 C555.2 C556.2 C557.2 C566.2 C567.1 C568.2 C569.2 C570.2 C571.2 C572.2 C578.2 C579.1 C583.1 C584.2 C585.2 C586.2 C587.2 C588.2 C589.2 C590.2 C591.2 C592.2 C593.2 C594.2 C595.2 C596.2 C597.2 C598.2 C599.2 C600.2 C601.2 C602.2 C603.2 C604.2 C605.2 C606.1 C607.1 C608.2 C609.2 C610.2 C611.2 C612.2 C613.2 C614.2 C615.2 C616.2 C617.2 C618.2 C619.2 C620.2 C621.2 C622.2 C623.2 C624.2 C625.2 C626.2 C627.2 C628.2 C629.2 C630.2 C631.2 C632.2 C633.2 C634.2 C635.1 C636.1 C637.1 C638.2 C639.1 C640.2 C643.1 C644.1 C645.2 C646.2 C647.2 C648.2 C649.2 C650.2 C651.2 C652.2 C653.2 C654.2 C655.2 C656.2 C657.2 C658.2 C659.2 C660.2 C661.2 C662.1 C663.1 C664.2 C665.1 C666.1 C668.2 C669.2 C670.2 C671.2 C672.2 C673.1 C674.1 C676.1 C677.1 C678.1 C679.1 C680.1 C681.1 C682.1 C683.1 C684.1 C685.1 C686.1 C687.1 C688.1 C689.1 C690.1 C691.1 C692.1 C693.1 C694.1 C695.1 C696.1 C697.1 C698.1 C699.1 C700.1 C701.1 C702.1 C703.1 C704.1 C705.1 C706.1 C707.1 C708.1 C709.1 D1.2 D2.2 D3.2 D4.2 D6.2 D7.2 D8.2 D9.1 D10.1 D501.1 D502.2 D503.2 D504.2 D505.2 D506.2 D507.2 D508.2 DN500.1 DN501.1 DN502.1 DN503.1 DN505.1 DN506.1 DN507.1 DN508.1 J1.4 J1.8 J1.10 J1.12 J2.G1 J2.G2 J2.G3 J2.G4 J2.G5 J2.G6 J2.G7 J2.G8 J3.G1 J3.G2 J3.G3 J3.G4 J3.G5 J3.G6 J3.G7 J3.G8 J5.4 J6.2 J7.2 J8.3 J9.6 J10.5 J17.2 J20.5 J21.5 J22.5 J23.7 J23.10 J23.15 J23.16 J24.1 J24.20 J25.2 J27.GND1 J27.GND2 J28.4 J28.6 J28.8 J28.10 J28.12 J28.14 J28.16 J28.18 J28.20 J29.4 J30.3 J31.3 J32.5 J32.G1 J32.G2 J32.G3 J32.G4 J32.G5 J33.9 J33.10 J33.11 J33.12 J35.3 J37.1 J37.3 J37.5 J37.7 J38.1 J39.5 J40.13 J40.14 J41.4 J42.3 J43.3 J44.3 J47.6 J48.2 J49.6 J50.2 J52.9 J52.10 J52.14 J53.2 J54.4 J55.4 J56.4 J57.3 J58.3 J59.3 J59.5 J59.7 J59.9 J59.11 J60.3 J62.3 J64.3 J65.3 J66.3 J67.3 J500.1A J500.1D J500.2C J500.2F J500.3A J500.3D J500.4C J500.4F J500.5A J500.5D J500.6C J500.6F J500.7A J500.7D J500.8C J500.8F J500.9A J500.9D J500.10C J500.10F J500.11A J500.11D J500.12C J500.12F J500.13D J500.14C J500.14F J500.15A J500.15D J500.16C J500.16F J500.17A J500.17D J500.18C J500.18F J500.19A J500.19D J500.20C J500.20F J500.21A J500.21D J500.22C J500.22F J500.23A J500.23D J500.24C J500.24F J500.25A J500.25D MT1.1 MT2.1 MT3.1 MT4.1 MT5.1 MT6.1 Q3.1 Q4.1 Q501.1 Q502.1 Q503.1 Q504.1 Q507.1 R5.2 R23.2 R34.2 R52.2 R510.1 R518.2 R520.2 R521.1 R524.1 R537.1 R542.1 R569.2 R571.1 R574.2 R585.1 R597.2 R598.1 R600.1 R640.1 R650.1 R664.1 R669.2 R670.1 R679.1 R681.1 R683.1 R688.2 R698.2 R703.2 R705.2 R710.1 R734.1 R755.2 R757.2 R769.1 R773.1 R788.1 R789.1 R790.1 R791.1 R792.1 R793.1 RN1.5 RN1.6 RN1.7 RN1.8 RN500.5 RN500.6 RN500.7 RN500.8 RN501.5 RN501.6 RN501.7 RN501.8 RN502.5 RN502.6 RN502.7 RN502.8 RN503.5 RN504.5 RN504.6 RN504.7 RN504.8 TP44.1 U1.2 U2.7 U2.19 U2.44 U3.3 U3.7 U4.8 U4.19 U4.38 U4.49 U5.2 U5.3 U6.15 U7.2 U7.11 U7.35 U7.41 U7.49 U7.55 U7.62 U7.69 U7.77 U7.87 U7.88 U7.89 U7.94 U8.1 U8.12 U8.13 U9.4 U10.4 U11.A1 U11.A2 U11.A3 U11.A17 U11.A18 U11.A24 U11.A25 U11.A26 U11.AA6 U11.AA9 U11.AA12 U11.AA15 U11.AA18 U11.AA21 U11.AB5 U11.AB14 U11.AB15 U11.AB16 U11.AB17 U11.AB22 U11.AC4 U11.AC6 U11.AC17 U11.AC18 U11.AC23 U11.AD3 U11.AD17 U11.AD18 U11.AD24 U11.AE3 U11.AE17 U11.AE24 U11.AE25 U11.AF1 U11.AF2 U11.AF3 U11.AF17 U11.AF24 U11.AF25 U11.AF26 U11.B1 U11.B2 U11.B3 U11.B17 U11.B18 U11.B25 U11.C3 U11.C18 U11.C24 U11.D4 U11.D17 U11.D18 U11.D23 U11.E5 U11.E15 U11.E16 U11.E17 U11.E22 U11.F6 U11.F9 U11.F12 U11.F15 U11.F18 U11.F21 U11.G5 U11.J5 U11.J6 U11.J21 U11.K5 U11.K26 U11.L5 U11.L12 U11.L13 U11.L14 U11.L15 U11.L23 U11.L25 U11.M6 U11.M11 U11.M12 U11.M13 U11.M14 U11.M15 U11.M16 U11.M21 U11.M22 U11.M25 U11.N5 U11.N11 U11.N12 U11.N13 U11.N14 U11.N15 U11.N16 U11.P11 U11.P12 U11.P13 U11.P14 U11.P15 U11.P16 U11.P24 U11.R5 U11.R6 U11.R11 U11.R12 U11.R13 U11.R14 U11.R15 U11.R16 U11.R24 U11.R26 U11.T12 U11.T13 U11.T14 U11.T15 U11.U5 U11.V5 U11.V6 U11.V21 U11.W5 U11.Y5 U12.15 U13.12 U13.34 U14.1 U14.33 U14.52 U14.56 U15.7 U15.19 U15.44 U16.4 U16.7 U18.3 U19.2 U20.19 U20.25 U21.2 U500.3 U501.8 U501.10 U502.2 U503.2 U503.5 U504.3 U505.7 U506.1 U506.2 U506.3 U506.4 U506.5 U506.11 U506.12 U506.13 U507.3 U508.14 U509.3 U510.8 U510.10 U510.11 U511.1 U511.3 U512.2 U512.8 U512.10 U513.1 U513.3 U514.1 U514.2 U515.4 U516.2 U516.3 U517.1 U517.12 U517.13 U518.8 U518.15 U519.1 U519.12 U519.13 U520.3 U521.4 U522.1 U522.3 U523.1 U523.3 U524.1 U524.3 U525.3 U526.1 U526.3 VR1.1 VR2.1
P5V: C3.1 C5.1 C684.2 C705.2 J2.9 J2.11 J3.9 J3.11 J20.8 J30.1 J58.1 J59.1 Q506.2 R19.1 R641.1 R713.2 R758.2 R775.1 R786.1 TP33.1
P5V_CONN: J37.4 R713.1
P5V_IR: C506.2 R508.1 U1.3
P5V_IR_CONN: C37.2 R66.1 U21.3
P12V: C18.1 C19.1 C505.2 C512.2 C519.2 C520.2 C527.2 C564.1 C638.1 C639.2 C641.2 C664.1 C665.2 C666.2 C672.1 C706.2 DN500.2 DN501.2 DN502.2 DN503.2 DN505.2 DN506.2 DN507.2 DN508.2 FB504.2 J23.2 J36.2 J39.1 J40.1 J40.2 J57.1 J500.15F J500.16A J500.16B Q5.2 Q5.4 R1.1 R11.2 R15.2 R634.2 R706.1 R714.1 R716.1 R730.2 R731.2 R732.2 R759.2 R760.2 R761.2 TP51.1 U2.9 U2.22 U2.23 U2.27 U2.37 U2.42 U2.43 U15.9 U15.22 U15.27 U15.37 U15.42 U505.2
P12V_FIL: C29.2 C32.1 FB8.2 J36.1 Q5.3 R37.2 R39.1 R40.1 TP53.1
P12V_IN: C28.2 FB8.1 J27.P12V_IN J37.6
VDD1_INDEX_SENSE: C703.2 J62.1 R780.1
VDD2_INDEX_SENSE: C704.2 J60.1 R781.1
VDD_TILT: C508.2 R512.1 U3.8
3D_TOGGLE: U11.E26 U519.8 U522.2
A1P8V: R527.1 R620.1
A1P8V_SENSE: C23.2 C642.2 R620.2 R633.1 R639.2 TP40.1 U15.29
A_BLU_PWM: J23.5 J24.7 U8.21
A_GRN_PWM: J23.3 J24.5 U8.22
A_LED4_PWM: J23.9 J24.2 U8.20
A_LED5_PWM: J23.11 J24.4 U8.19
A_LED6_PWM: J23.13 J24.6 U8.18
A_LED7_PWM: J23.17 J24.11 U8.17
A_LED8_PWM: J23.19 J24.13 U8.16
A_RED_PWM: J23.1 J24.3 U8.23
A_SPARE_1: J23.18 J38.2 U519.23
A_SPARE_2: J23.22 U8.15
A_SPARE_3: J23.20 U8.14
A_SSP0_CLK: R27.2 R28.2 TP56.1 U11.AD4
A_SSP0_TXD: R29.2 R30.2 TP57.1 U11.AB7
ADC_CSZ: J59.10 R623.1 TP62.1
ADC_RST/COMP_PWM: J59.2 R622.1 R708.2 TP66.1
ADC_SCLK: J59.4 R624.1 TP65.1
ADC_SDIN: J26.1 J59.6 TP64.1
ADC_SDO: J34.1 J59.8 TP63.1
ADCINA0: C539.1 J11.4 R572.1 U7.23
ADCLO: R586.2 U7.24
ADCREFM: C575.1 TP27.1 U7.36
ADCREFP: C574.1 TP28.1 U7.37
ADCRESEXT: R583.1 U7.38
AFE_CLK: R604.2 U11.AD12
AFE_RSTZ: J3.108 R8.1 U11.AC12
ALF_CLAMP: J3.116 U11.AB12
ALF_COAST: J3.118 U11.AC11
ALF_CSYNC: J3.49 TP2.1 U11.AE11
ALF_HSYNC: J3.51 TP32.1 U11.AD11
ALF_VSYNC: J3.50 TP1.1 U11.AF11
BLU_LED_EN: J45.1 RN500.3 U7.71 U519.7
BLU_PWM: RN502.2 U8.4 U11.C20
BT656_A_CLK: J3.94 U4.5
BT656_A_D0: J3.105 U4.28
BT656_A_D1: J3.104 U4.26
BT656_A_D2: J3.103 U4.24
BT656_A_D3: J3.102 U4.22
BT656_A_D4: J3.101 U4.20
BT656_A_D5: J3.100 U4.16
BT656_A_D6: J3.99 U4.14
BT656_A_D7: J3.98 U4.12
BT656_A_D8: J3.97 U4.10
BT656_A_D9: J3.96 U4.7
BT656_B_CLK: J2.94 U4.4
BT656_B_D0: J2.105 U4.27
BT656_B_D1: J2.104 U4.25
BT656_B_D2: J2.103 U4.23
BT656_B_D3: J2.102 U4.21
BT656_B_D4: J2.101 U4.18
BT656_B_D5: J2.100 U4.15
BT656_B_D6: J2.99 U4.13
BT656_B_D7: J2.98 U4.11
BT656_B_D8: J2.97 U4.9
BT656_B_D9: J2.96 U4.6
BT656_CLK: R549.2 U4.52
BT656_D0: R559.2 U4.30
BT656_D1: R558.2 U4.32
BT656_D2: R557.2 U4.34
BT656_D3: R556.2 U4.36
BT656_D4: R555.2 U4.39
BT656_D5: R554.2 U4.41
BT656_D6: R553.2 U4.43
BT656_D7: R552.2 U4.45
BT656_D8: R551.2 U4.47
BT656_D9: R550.2 U4.50
BUS_SELECT: J3.89 R757.1 U20.16
COMP_SENSE_INPUT: J31.2 R719.1 U515.2
COMP_SENSE_VDD: C682.2 J31.1 R718.1
COMP_SENSOR: J26.3 R720.1 R721.1 U515.1
CSZ5_DAD2: J500.12B R57.1
CW_INDEX1: R762.1 R763.1 TP69.1 U11.AF7 U521.1
CW_INDEX2: R591.2 R765.1 R767.1 TP68.1 U521.7
CW_PWM1: R24.1 U11.AD8
CW_PWM2/SPD4: R514.1 U11.H26 U517.7
CWCTR1: C580.1 C581.1 C582.1 DN508.3 J63.1 U15.13
CWCTR2: C500.1 C501.1 C502.1 DN502.3 J61.1 U2.13
CWY1A: DN505.3 J63.4 R601.2 R632.2
CWY1B: DN506.3 J63.3 R18.2 R602.2
CWY1C: DN507.3 J63.2 R20.2 R589.2
CWY2A: DN500.3 J61.4 R6.2 R500.2
CWY2B: DN501.3 J61.3 R4.2 R501.2
CWY2C: DN503.3 J61.2 R3.2 R502.2
D_PWM_0: J24.17 J39.6 U506.19
D_PWM_1: J24.19 J39.7 U506.18
D_PWM_2: J24.16 J39.8 U506.17
D_PWM_3: J24.18 J39.9 U506.16
D_SPARE_1: J38.10 U519.16
D_SPARE_2: J38.11 U519.15
DA0: C648.1 R646.1 U11.AB8
DA1: C649.1 R647.1 U11.AF4
DA2: C651.1 R689.1 U11.AE5
DA3: C654.1 R653.1 U11.AD6
DADADD0: J500.13E R646.2
DADADD1: J500.13F R647.2
DADADD2: J500.14A R689.2
DADADD3: J500.14B R653.2
DADINTZ: J500.15E R621.2
DADMD0: J500.15B R652.2
DADMD1: J500.15C R645.2
DADOEZ: J500.12E R651.2
DADSEL0: J500.14D R644.2
DADSEL1: J500.14E R648.2
DADSTB: J500.13C R654.2 TP55.1
DASYNC: J9.4 R531.2
DB/RED_PWM: R769.2 RN500.4 U7.53 U8.2 U11.B19 U523.2
DCLKA_N: J500.5C U11.V3
DCLKA_P: J500.5B U11.V4
DCLKB_N: J500.21C U11.J4
DCLKB_P: J500.21B U11.J3
DDA00_N: J500.10E U11.P3
DDA00_P: J500.10D U11.P4
DDA01_N: J500.9C U11.P1
DDA01_P: J500.9B U11.P2
DDA02_N: J500.9F U11.R3
DDA02_P: J500.9E U11.R4
DDA03_N: J500.8B U11.R1
DDA03_P: J500.8A U11.R2
DDA04_N: J500.8E U11.T3
DDA04_P: J500.8D U11.T4
DDA05_N: J500.7C U11.T1
DDA05_P: J500.7B U11.T2
DDA06_N: J500.7F U11.U3
DDA06_P: J500.7E U11.U4
DDA07_N: J500.6B U11.U1
DDA07_P: J500.6A U11.U2
DDA08_N: J500.5F U11.W3
DDA08_P: J500.5E U11.W4
DDA09_N: J500.4B U11.W1
DDA09_P: J500.4A U11.W2
DDA10_N: J500.4E U11.Y1
DDA10_P: J500.4D U11.Y2
DDA11_N: J500.3C U11.Y3
DDA11_P: J500.3B U11.Y4
DDA12_N: J500.3F U11.AA1
DDA12_P: J500.3E U11.AA2
DDA13_N: J500.2B U11.AA3
DDA13_P: J500.2A U11.AA4
DDA14_N: J500.2E U11.AB1
DDA14_P: J500.2D U11.AB2
DDA15_N: J500.1F U11.AC1
DDA15_P: J500.1E U11.AC2
DDB00_N: J500.16E U11.N2
DDB00_P: J500.16D U11.N1
DDB01_N: J500.17C U11.N4
DDB01_P: J500.17B U11.N3
DDB02_N: J500.17F U11.M1
DDB02_P: J500.17E U11.M2
DDB03_N: J500.18B U11.M4
DDB03_P: J500.18A U11.M3
DDB04_N: J500.18E U11.L2
DDB04_P: J500.18D U11.L1
DDB05_N: J500.19C U11.L4
DDB05_P: J500.19B U11.L3
DDB06_N: J500.19F U11.K2
DDB06_P: J500.19E U11.K1
DDB07_N: J500.20B U11.K4
DDB07_P: J500.20A U11.K3
DDB08_N: J500.22B U11.H2
DDB08_P: J500.22A U11.H1
DDB09_N: J500.21F U11.H4
DDB09_P: J500.21E U11.H3
DDB10_N: J500.22E U11.G2
DDB10_P: J500.22D U11.G1
DDB11_N: J500.23C U11.G4
DDB11_P: J500.23B U11.G3
DDB12_N: J500.23F U11.F2
DDB12_P: J500.23E U11.F1
DDB13_N: J500.24B U11.F4
DDB13_P: J500.24A U11.F3
DDB14_N: J500.24E U11.E2
DDB14_P: J500.24D U11.E1
DDB15_N: J500.25C U11.D2
DDB15_P: J500.25B U11.D1
DINTZ: C611.1 R621.1 U11.AC8
DM0: C653.1 R652.1 U11.AE6
DM1: C647.1 R645.1 U11.AD7
DMD_P3P3V: C31.2 C35.2 FB9.1 FB10.1 J51.2 R35.1 R58.1
DMDP3P3VA: C36.2 FB10.2 J500.1B J500.1C
DMDP3P3VB: C30.2 FB9.2 J500.25E J500.25F
DMDSPARE0: J500.12D R34.1
DOEZ: C652.1 R651.1 U11.AE7
DRV_RST: J39.12 U506.15
DRV_RST/SSP2_CSZ_1: U11.K22 U518.13
DS0: C646.1 R644.1 U11.AC7
DS1: C650.1 R648.1 U11.AE4
DSP_A1P8V: C558.1 C561.1 C573.1 FB501.1 U7.12 U7.40
DSP_A3P3V: C559.1 C560.1 C562.1 C563.1 FB503.1 U7.15 U7.26
DSP_EMU0: J1.13 R535.2 U7.80
DSP_EMU1: J1.14 R503.2 U7.81
DSP_GPIO11: RN501.3 U7.70
DSP_GPIO12: TP4.1 U7.1
DSP_GPIO13: TP5.1 U7.95
DSP_GPIO14: TP18.1 U7.8
DSP_GPIO23: RN501.2 U7.72 U519.9
DSP_GPIO26: RN501.1 U7.99 U519.10
DSP_INTZ: J14.1 RN503.3 U7.61
DSP_P1P8V: C10.1 C13.1 C530.1 C532.1 C533.1 C537.1 C557.1 C572.1 FB501.2 J2.6 J2.8 J3.6 J3.8 J18.2 U7.10 U7.42 U7.59 U7.68 U7.85 U7.93
DSP_P3P3V: C531.1 C534.1 C535.1 C536.1 C538.1 C556.1 C571.1 FB502.1 J1.5 R503.1 R535.1 R564.1 R566.1 R567.1 R568.1 U7.3 U7.46 U7.65 U7.82 U7.96
DSP_PWM_0: RN1.1 U7.47 U506.6
DSP_PWM_1: RN1.2 U7.44 U506.7
DSP_PWM_2: RN1.3 U7.45 U506.8
DSP_PWM_3: RN1.4 U7.48 U506.9
DSP_RDY: J13.1 RN501.4 U7.60
DSP_RSTZ: J8.2 U7.78
DSP_TCK: J1.9 J1.11 R565.1 R566.2 U7.75
DSP_TDI: J1.3 R567.2 U7.73
DSP_TDO: R534.1 U7.76
DSP_TDO_OUT: J1.7 R534.2 R564.2
DSP_TMS: J1.1 R568.2 U7.74
DSP_TRSTZ: J1.2 R569.1 U7.84
DSTB: C655.1 R654.1 U11.AF5
DYN_BLK_BUF: R768.2 U523.4
EXT_ARSTZ: J8.1 J500.11F R7.2 R9.1 R776.1 TP6.1 U11.T24
EXT_CLK: J3.52 R604.1
FAN1_LOCKD: J64.2 R63.1 U11.B24
FAN1_SW: D508.1 L506.2 R779.1 U15.40
FAN2_LOCKD: J65.2 R64.1 U11.D21
FAN2_SW: D507.1 L505.2 R778.1 U15.39
FAN3_LOCKD: J66.2 R65.1 U11.C23
FAN3_SW: D506.1 L504.2 R777.1 U15.38
FAN4_LOCKD: J42.2 R49.1 R605.2
FAN4_SW: D505.1 L503.2 R744.1 U2.40
FAN5_LOCKD: J43.2 R50.1 R595.2
FAN5_SW: D504.1 J4.1 L502.2 R743.1 U2.39
FAN6_LOCKD: J44.2 R51.1 R607.2
FAN6_SW: D503.1 J4.3 L501.2 R742.1
FAN6_SW_JUMP: J4.2 U2.38
FE_P1P2V: C9.1 C12.1 J2.2 J2.4 J3.2 J3.4 J19.2
FE_RST: J41.1 R48.2 U18.2
FIELD: J3.88 J41.3 U11.AF9
FLASH_A19_A21: R702.2 R704.2 U14.11
FLASH_A21_VPP: R700.1 R701.2 U14.15
FLASH_CSSZ: R609.2 U14.32
FLASH_CSZ: R609.1 U11.E12
FLASH_RSTZ: R577.1 R578.1 U14.14
FREQ_SENSOR: J30.2 J34.3
FSD12: J9.3 R562.2
GPIO_09: J14.2 U11.B21
GPIO_10: J13.2 U11.A22
GPIO_12: R528.1 R545.1 U11.B22
GPIO_13: R529.1 R546.1 U11.C21
GPIO_21: RN506.3 U8.10 U11.E20
GPIO_23: RN506.4 U8.11 U11.E21
GPIO_24: J12.2 U11.B26
GPIO_26: J45.2 U11.D24
GPIO_30: R796.2 U11.D25
GPIO_32: R795.2 U11.E24
GPIO_33: R794.2 U11.D26
GPIO_40: R559.1 R562.1 U11.T23
GPIO_41: R531.1 R558.1 U11.R22
GPIO_42: R557.1 U11.U26
GPIO_43: R532.1 R556.1 U11.U25
GPIO_44: R555.1 R563.1 U11.U24
GPIO_45: R554.1 U11.U23
GPIO_46: R553.1 U11.T22
GPIO_47: R552.1 U11.V26
GPIO_48: R551.1 U11.V25
GPIO_49: R550.1 U11.V24
GPIO_50: R549.1 U11.V23
GPIO_54: RN504.4 U11.F26 U519.2
GPIO_60: R596.1 R605.1 U11.H22
GPIO_61: R594.1 R595.1 U11.H23
GPIO_62: R592.1 R593.1 U11.H24
GPIO_63: R590.1 R591.1 U11.H25
GPIO_65: R606.1 R607.1 U11.J22
GPIO_74: J26.2 U11.AE10
GPIO_75: J34.2 R625.1
GPIOX_11: R59.1 U20.12
GPIOX_12: R60.1 U20.13
GPIOX_13: R61.1 U20.14
GPIOX_14: R62.1 U20.15
GPIOX_INT: U11.E3 U20.24
GPIOX_RST: R755.1 U11.G22 U20.20
GRN_LED_EN: RN500.2 U7.67 U11.C25 U519.6
GRN_PWM: RN502.1 U8.3 U11.B20
HBT_CLK_IN1: J9.1 R563.2
HBT_DI1: J9.2 R532.2
HDMI_CEC: J3.13 TP7.1 U11.G23
HDMI_HPD: J3.90 U20.10
HDMI_INT: J3.91 TP20.1 U11.AB13
HOLD_BOOTZ: J17.1 R560.2 U11.F24
I2C_BUSY: J41.2 R745.2 U11.G24
ICE_RSTZ: J28.15 J32.9 R712.1 U513.2 U514.4
ICTSEN: R597.1 U11.M24
INDEX1_SENSE_INPUT: J62.2 R764.1 U521.2
INDEX2_SENSE_INPUT: J60.2 R766.1 U521.6
IR0: U11.C26 U500.4
IR1: U11.E23 U520.4
KEYPD_DOWN: J52.4 R741.1 U20.2
KEYPD_LED_HOT: R739.2 U20.9
KEYPD_LED_LMP: R738.2 U20.8
KEYPD_LED_PWR: R737.2 U20.7
KEYPD_LEFT: J52.5 R736.1 U20.3
KEYPD_PWR: J52.7 R612.1 R735.1 U20.1
KEYPD_RIGHT: J52.6 R740.1 U20.4
KEYPD_SEL: J52.2 R754.1 U20.6
KEYPD_UP: J52.3 R752.1 U20.5
LAMPLITZ: J38.4 J39.10 J53.1 R783.1 R784.1
LAMPLITZ_FLTR: C708.2 R784.2 TP71.1 U524.2
LED1_GRN: D11.1 R60.2
LED1_RED: D11.4 R59.2
LED2_GRN: D12.1 R62.2
LED2_RED: D12.4 R61.2
LED4_PWM: RN502.3 U8.5 U11.A20
LED5_PWM: RN502.4 U8.6 U11.A21
LED6_PWM: J14.3 RN504.1 U8.7
LED7_PWM: J13.3 RN504.2 U8.8
LED8_PWM: RN504.3 U8.9 U11.A23
LED_DIR: J49.5 R749.2 TP58.1
LED_DOUT: J49.3 R746.2 TP60.1
LED_DRV_DIR: RN505.4 U7.6 U518.14
LED_DRV_DOUT: RN505.2 U7.52 U518.5
LED_DRV_OE: RN505.3 U7.57 U518.11
LED_DRV_SCLK: R582.1 U7.54 U518.2
LED_EN: J38.3 J39.11 J46.2
LED_OE: J49.4 R750.2 TP59.1
LED_SCLK: J49.1 R748.2 TP61.1
LMP_HOT: J7.1 J12.3 R533.2
LMP_TXD: J45.3 R772.1 R773.2 U526.2
LMP_TXD_BUF: J53.5 R787.1
LMPCTRL: R687.2 R688.1 TP31.1 U11.AC9 U511.2 U519.3
LMPCTRL_BUF: J53.6 R643.1
LMPCTRL_Z: J53.4 R686.1
LMPSTAT: U11.AF8 U524.4
LP_DRIVE: R599.1 R600.2 U508.5
LP_IR0: R614.1 R616.1 U1.1 U500.2
LP_IR1: R615.1 R619.1 U21.1 U520.2
LP_P1_0: R612.2 U508.2
LP_P1_5: R616.2 U508.7
LP_P1_6: R619.2 U508.8
LP_P2_6: R617.2 U508.13
LP_P2_7: R618.2 U508.12
LP_P3P3V: C503.2 C504.2 R504.1 R505.1 U500.5 U520.5
LP_TA0: R613.2 R614.2 U508.3
LP_TA1: R615.2 U508.4
LP_TCK: J22.2 R631.1
LP_TDO_TDI: C637.2 J22.4 R629.1 U508.10
LP_TEST_VPP: J22.3 R631.2 U508.11
M_FUT_0: RN503.4 U7.58 U506.10
MAN_RSTZ: J25.1 R711.1 SW1.3 U514.3
MC_VCC: C578.1 C607.2 R611.2 R629.2 U508.1
MODEB: J50.1 J500.11B R58.2
MTR_ARSTZ: R26.2 TP17.1 U2.48 U11.T25 U15.48
NC0001: J3.3
NC0002: J3.48
NC0003: J3.106
NC0004: J3.107
NC0005: J3.109
NC0006: J3.110
NC0007: J3.111
NC0008: J3.112
NC0009: J3.120
NC0010: U509.4
NC0011: J20.3
NC0012: J2.1
NC0013: J2.3
NC0014: J2.13
NC0015: J2.14
NC0016: J2.15
NC0017: J2.16
NC0018: J2.17
NC0019: J2.18
NC0020: J2.19
NC0021: J2.20
NC0022: J2.21
NC0023: J2.22
NC0024: J2.23
NC0025: J2.24
NC0026: J2.25
NC0027: J2.26
NC0028: J2.27
NC0029: J2.28
NC0030: J2.29
NC0031: J2.30
NC0032: J2.31
NC0033: J2.32
NC0034: J2.33
NC0035: J2.34
NC0036: J2.35
NC0037: J2.36
NC0038: J2.37
NC0039: J2.38
NC0040: J2.39
NC0041: J2.40
NC0042: J2.41
NC0043: J2.42
NC0044: J2.43
NC0045: J2.44
NC0046: J2.45
NC0047: J2.46
NC0048: J2.47
NC0049: J2.48
NC0050: J2.49
NC0051: J2.50
NC0052: J2.51
NC0053: J2.52
NC0054: J2.53
NC0055: J2.54
NC0056: J2.55
NC0057: J2.56
NC0058: J2.57
NC0059: J2.58
NC0060: J2.59
NC0061: J2.60
NC0062: J2.61
NC0063: J2.62
NC0064: J2.63
NC0065: J2.64
NC0066: J2.65
NC0067: J2.66
NC0068: J2.67
NC0069: J2.68
NC0070: J2.69
NC0071: J2.70
NC0072: J2.71
NC0073: J2.72
NC0074: J2.73
NC0075: J2.74
NC0076: J2.75
NC0077: J2.76
NC0078: J2.77
NC0079: J2.78
NC0080: J2.79
NC0081: J2.80
NC0082: J2.81
NC0083: J2.82
NC0084: J2.83
NC0085: J2.84
NC0086: J2.85
NC0087: J2.86
NC0088: J2.87
NC0089: J2.88
NC0090: J2.89
NC0091: J2.90
NC0092: J2.91
NC0093: J2.93
NC0094: J2.95
NC0095: J2.106
NC0096: J2.107
NC0097: J2.108
NC0098: J2.109
NC0099: J2.110
NC0100: J2.111
NC0101: J2.112
NC0102: J2.113
NC0103: J2.114
NC0104: J2.116
NC0105: J2.118
NC0106: J2.119
NC0107: J2.120
NC0108: J500.13B
NC0109: J500.13A
NC0110: U17.5
NC0111: U17.8
NC0112: J35.2
NC0113: D10.3
NC0114: D10.4
NC0115: U510.13
NC0116: U510.14
NC0117: U510.12
NC0118: J67.2
NC0119: J59.12
NC0120: U4.3
NC0121: U4.2
NC0122: U4.29
NC0123: U4.31
NC0124: U4.33
NC0125: U4.35
NC0126: U4.37
NC0127: U4.40
NC0128: U4.42
NC0129: U4.44
NC0130: U4.46
NC0131: U4.48
NC0132: U4.51
NC0133: U4.53
NC0134: U4.54
NC0135: U7.86
NC0136: U7.97
NC0137: U7.98
NC0138: U7.22
NC0139: U7.21
NC0140: U7.20
NC0141: U7.19
NC0142: U7.18
NC0143: U7.17
NC0144: U7.16
NC0145: U7.30
NC0146: U7.31
NC0147: U7.32
NC0148: U7.33
NC0149: U7.34
NC0150: U7.9
NC0151: U7.83
NC0152: U7.91
NC0153: U7.79
NC0154: U7.7
NC0155: J1.6
NC0156: U20.11
NC0157: U502.1
NC0158: RN507.6(A)
NC0159: RN507.7(A)
NC0160: RN507.8(A)
NC0161: RN507.9(B)
NC0162: RN507.10(B)
NC0163: RN507.11(B)
NC0164: J32.1
NC0165: J32.2
NC0166: J32.3
NC0167: J32.4
NC0168: J32.7
NC0169: J32.8
NC0170: J32.10
NC0171: J32.23
NC0172: J32.25
NC0173: J32.27
NC0174: J32.29
NC0175: J32.31
NC0176: J32.33
NC0177: J32.35
NC0178: J32.37
NC0179: U503.1
NC0180: U503.3
NC0181: J21.9
NC0182: J10.9
NC0183: U14.55
NC0184: U14.28
NC0185: U14.30
NC0186: U16.1
NC0187: U16.2
NC0188: U5.1
NC0189: U5.4
NC0190: U3.1
NC0191: U3.6
NC0192: U506.23
NC0193: U506.22
NC0194: U506.21
NC0195: U506.20
NC0196: U506.14
NC0197: U525.1
NC0198: U11.A13
NC0199: J28.17
NC0200: J28.19
NC0201: U18.1
NC0202: U2.29
OCLKA: R603.1 U2.6 U15.6
OCLKA_RES: R603.2 U11.AF6
OUT1A: R632.1 U15.12
OUT1A_SNUB: C580.2 R601.1
OUT1B: R18.1 U15.15
OUT1B_SNUB: C581.2 R602.1
OUT1C: R20.1 U15.16
OUT1C_SNUB: C582.2 R589.1
OUT2A: R6.1 U2.12
OUT2A_SNUB: C500.2 R500.1
OUT2B: R4.1 U2.15
OUT2B_SNUB: C501.2 R501.1
OUT2C: R3.1 U2.16
OUT2C_SNUB: C502.2 R502.1
P1_A0: J3.85 U11.AE12
P1_A1: J3.84 U11.AF12
P1_A2: J3.83 U11.AF13
P1_A3: J3.82 U11.AF14
P1_A4: J3.81 U11.AC13
P1_A5: J3.80 U11.AD13
P1_A6: J3.79 U11.AE13
P1_A7: J3.78 U11.AE14
P1_A8: J3.77 U11.AE15
P1_A9: J3.76 U11.AD15
P1_B0: J3.75 U11.AD14
P1_B1: J3.74 U11.AC14
P1_B2: J3.73 U11.AF15
P1_B3: J3.72 U11.AF16
P1_B4: J3.71 U11.AE16
P1_B5: J3.70 U11.AD16
P1_B6: J3.69 U11.AC16
P1_B7: J3.68 U11.AC15
P1_B8: J3.67 U11.AB18
P1_B9: J3.66 U11.AF18
P1_C0: J3.65 U11.AE18
P1_C1: J3.64 U11.AC19
P1_C2: J3.63 U11.AF20
P1_C3: J3.62 U11.AF19
P1_C4: J3.61 U11.AE19
P1_C5: J3.60 U11.AD19
P1_C6: J3.59 U11.AF21
P1_C7: J3.58 U11.AE21
P1_C8: J3.57 U11.AE20
P1_C9: J3.56 U11.AD20
P1_HSYNC: J3.86 TP12.1 U11.AD21
P1_VSYNC: J3.55 TP14.1 U11.AC20
P1P1V: C27.2 C570.1 C585.1 C586.1 C587.1 C591.1 C592.1 C594.1 C596.1 C598.1 C599.1 C602.1 C604.1 C608.1 C609.1 C612.1 C614.1 C616.1 C618.1 C620.1 C622.1 C625.1 C626.1 C628.1 C631.1 C633.1 C634.1 C667.2 C668.1 J19.1 R25.2 R526.1 R678.2 R682.2 TP43.1 U11.AA8 U11.AA11 U11.AA14 U11.AA17 U11.AA20 U11.F7 U11.F10 U11.F13 U11.F16 U11.F19 U11.G21 U11.H6 U11.K21 U11.L6 U11.L11 U11.L16 U11.N21 U11.P6 U11.T11 U11.T16 U11.T21 U11.U6 U11.W21 U11.Y6
P1P2V_PMD2: C17.2 C510.2 J19.3 R509.2 R523.2 R525.2 TP16.1
P1P8V: C569.1 C589.1 C593.1 C600.1 C605.1 C617.1 C619.1 C621.1 C623.1 C624.1 C627.1 C632.1 C656.1 C657.1 C658.1 C659.1 C660.1 C661.1 C669.1 C670.1 C671.1 J18.1 R717.1 TP48.1 U11.AA5 U11.AA13 U11.AE1 U11.C1 U11.F5 U11.F14 U11.G6 U11.H5 U11.H21 U11.K6 U11.M5 U11.N6 U11.P5 U11.P21 U11.T5 U11.T6 U11.U21 U11.W6
P1P8V_PMD2: J18.3 R576.1 TP22.1
P2_A0: J3.45 U11.AB19
P2_A1: J3.44 U11.AE23
P2_A2: J3.43 U11.AD22
P2_A3: J3.42 U11.AC21
P2_A4: J3.41 U11.AB20
P2_A5: J3.40 U11.AD23
P2_A6: J3.39 U11.AC22
P2_A7: J3.38 U11.AB21
P2_A8: J3.37 U11.AD25
P2_A9: J3.36 U11.AD26
P2_B0: J3.35 U11.AC24
P2_B1: J3.34 U11.AC25
P2_B2: J3.33 U11.AB23
P2_B3: J3.32 U11.AC26
P2_B4: J3.31 U11.AB24
P2_B5: J3.30 U11.AA22
P2_B6: J3.29 U11.AB25
P2_B7: J3.28 U11.AA23
P2_B8: J3.27 U11.AB26
P2_B9: J3.26 U11.Y22
P2_C0: J3.25 U11.AA24
P2_C1: J3.24 U11.AA25
P2_C2: J3.23 U11.AA26
P2_C3: J3.22 U11.W22
P2_C4: J3.21 U11.Y23
P2_C5: J3.20 U11.Y24
P2_C6: J3.19 U11.Y25
P2_C7: J3.18 U11.Y26
P2_C8: J3.17 U11.V22
P2_C9: J3.16 U11.W23
P2_HSYNC: J3.46 TP9.1 U11.W26
P2_VSYNC: J3.15 TP23.1 U11.U22
P2P5V: C11.1 C14.1 J2.10 J2.12 J3.10 J3.12 Q505.2 Q505.4 R31.1 R33.2 TP47.1
P2P5V_CONN: J37.8 R14.2 R31.2
P2P5V_PMD2: Q500.2 Q500.4 R14.1 R17.2 TP21.1
P3P3V: C2.1 C4.1 C26.2 C34.2 C509.2 C516.2 C523.2 C525.1 C526.2 C552.1 C555.1 C567.2 C568.1 C588.1 C590.1 C595.1 C597.1 C601.1 C603.1 C606.2 C610.1 C613.1 C615.1 C629.1 C630.1 C635.2 C636.2 C662.2 C663.2 C673.2 C679.2 C681.2 C683.2 C685.2 C686.2 C687.2 C688.2 C692.2 C693.2 C694.2 C695.2 C696.2 C697.2 C698.2 C707.2 D11.2 D11.3 D12.2 D12.3 DN504.3(TP-3) FB500.2 FB502.2 FB503.2 J2.5 J2.7 J3.5 J3.7 J28.1 J28.2 J29.1 J32.12 J32.14 J51.1 J54.3 J55.3 J56.3 R7.1 R16.2 R26.1 R32.2 R36.2 R48.1 R49.2 R50.2 R51.2 R53.1 R63.2 R64.2 R65.2 R504.2 R507.2 R512.2 R517.1 R519.1 R530.1 R533.1 R538.2 R541.2 R543.2 R544.1 R547.1 R548.1 R560.1 R561.1 R570.2 R582.2 R584.2 R608.1 R610.1 R626.2 R627.1 R642.1 R655.1 R656.1 R657.1 R658.1 R659.1 R665.1 R667.2 R672.1 R674.1 R676.1 R691.2 R692.2 R696.1 R699.1 R700.2 R711.2 R712.2 R718.2 R719.2 R721.2 R723.2 R724.2 R725.2 R727.2 R728.2 R729.2 R733.2 R735.2 R736.2 R740.2 R741.2 R745.1 R747.2 R751.2 R752.2 R753.2 R754.2 R756.2 R762.2 R764.2 R766.2 R767.2 R770.1 R771.1 R772.2 R774.1 R780.2 R781.2 R783.2 R785.1 RN503.6 RN503.7 RN503.8 RN505.5 RN505.6 RN505.7 RN505.8 RN506.5 RN506.6 RN506.7 RN506.8 TP50.1 U3.4 U4.17 U8.24 U9.1 U9.7 U10.1 U10.7 U11.AA7 U11.AA10 U11.AA16 U11.AA19 U11.AE26 U11.F8 U11.F11 U11.F17 U11.F20 U11.L21 U11.R21 U11.Y21 U12.16 U13.11 U13.33 U14.43 U16.3 U16.8 U18.5 U19.3 U19.4 U19.5 U20.21 U504.5 U506.24 U507.6 U509.6 U513.5 U514.5 U515.8 U516.5 U517.24 U518.16 U519.24 U521.8 U522.5 U523.5 U524.5 U525.5 VR1.3 VR2.3
P3P3V_CONN: J37.2 R53.2 R638.2 R685.2
P3P3V_EX: J51.3 R587.2
P3P3V_LP: C33.2 C579.2 C643.2 R38.1 R505.2 R506.2 R511.2 R540.2 R611.1 R630.1 R637.2 R684.2 TP500.1 U17.2 U17.3 U17.6 U17.7
P_CLK1: J3.54 TP8.1 U11.AE22
P_CLK2: J3.14 TP10.1 U11.W25
P_CLK3: J3.119 TP13.1 U11.AF23
P_DATAEN1: J3.87 TP15.1 U11.AF22
P_DATAEN2: J3.47 TP11.1 U11.W24
P_INTZ: R675.1 U2.36
PACKET_RDY: J20.9 R788.2 TP38.1 U11.F25 U509.2
PB_INDEX: J29.2 U11.AE9
PB_IR_ENABLE: J29.3 U11.AD9
PB_SPARE: J20.10 R793.2 TP30.1 U11.AB10 U509.1
PGOOD: R673.1 U2.35
PIPESTAT0: J32.38 RN507.14(B)
PIPESTAT0R: RN507.3(A) U11.C6
PIPESTAT1: J32.36 RN507.15(B)
PIPESTAT1R: RN507.2(A) U11.B5
PIPESTAT2: J32.34 RN507.16(B)
PIPESTAT2R: RN507.1(A) U11.A4
PLLD_VAD: C550.1 FB1.2 U11.K25
PLLD_VDD: C546.1 FB5.2 U11.L22
PLLM1_VAD: C548.1 FB2.2 U11.L24
PLLM1_VDD: C547.1 FB4.2 U11.L26
PLLM2_VAD: C549.1 FB3.2 U11.R25
PLLM2_VDD: C645.1 FB6.2 U11.P23
PLLS_VAD: C584.1 FB7.2 U11.R23
PLUG_DETECT: J20.7 R664.2 TP39.1 U11.F23 U509.5
PM_ADR_0: U11.C7 U13.5 U14.31
PM_ADR_1: U11.A7 U13.4 U14.26
PM_ADR_2: U11.B7 U13.3 U14.25
PM_ADR_3: U11.C8 U13.2 U14.24
PM_ADR_4: U11.D8 U13.1 U14.23
PM_ADR_5: U11.A8 U13.44 U14.22
PM_ADR_6: U11.B8 U13.43 U14.21
PM_ADR_7: U11.C9 U13.42 U14.20
PM_ADR_8: U11.D9 U13.28 U14.10
PM_ADR_9: U11.E9 U13.27 U14.9
PM_ADR_10: U11.A9 U13.26 U14.8
PM_ADR_11: U11.B9 U13.25 U14.7
PM_ADR_12: U11.C10 U13.24 U14.6
PM_ADR_13: U11.D10 U13.23 U14.5
PM_ADR_14: U11.E10 U13.22 U14.4
PM_ADR_15: U11.C11 U13.21 U14.3
PM_ADR_16: U11.D11 U13.20 U14.54
PM_ADR_17: U11.A11 U13.19 U14.19
PM_ADR_18: U11.B11 U13.18 U14.18
PM_ADR_19: R697.1 R704.1 U11.C12
PM_ADR_20: U11.D12 U14.12
PM_ADR_21: R701.1 R702.1 R703.1 U11.E11
PM_ADR_22: R705.1 U11.A12 U14.2
PM_BLS0: R661.1 U11.A6
PM_BLS0S: R661.2 U13.39
PM_BLS1: R662.1 U11.B6
PM_BLS1S: R662.2 U13.40
PM_DAT_0: U11.B13 U13.7 U14.35
PM_DAT_1: U11.C14 U13.8 U14.37
PM_DAT_2: U11.D14 U13.9 U14.39
PM_DAT_3: U11.E13 U13.10 U14.41
PM_DAT_4: U11.A14 U13.13 U14.44
PM_DAT_5: U11.B14 U13.14 U14.46
PM_DAT_6: U11.C15 U13.15 U14.48
PM_DAT_7: U11.D15 U13.16 U14.50
PM_DAT_8: U11.E14 U13.29 U14.36
PM_DAT_9: U11.C16 U13.30 U14.38
PM_DAT_10: U11.D16 U13.31 U14.40
PM_DAT_11: U11.B15 U13.32 U14.42
PM_DAT_12: U11.A15 U13.35 U14.45
PM_DAT_13: U11.A16 U13.36 U14.47
PM_DAT_14: U11.B16 U13.37 U14.49
PM_DAT_15: U11.C17 U13.38 U14.51
PM_OESZ: R663.2 U13.41 U14.34
PM_OEZ: R663.1 U11.C13
PM_SRAM_CSSZ: R660.2 U13.6
PM_SRAM_CSZ: R660.1 U11.D13
PM_WESZ: R628.2 U13.17 U14.13
PM_WEZ: R628.1 U11.B12
PMD1K2_CP1: C6.1 U2.18
PMD1K2_CP2: C6.2 U2.17
PMD1K2_FB_P2P5V: C545.2 L3.2 R17.1 U2.46
PMD1K2_GD_CORE: Q1.1 U2.26
PMD1K2_VCP: C505.1 U2.21
PMD1K2_VREG: C513.1 U2.20 U2.24 U2.31 U2.45 U2.47
PMD1K_CP1: C24.1 U15.18
PMD1K_CP2: C24.2 U15.17
PMD1K_FB_LIN1: C642.1 R633.2 R669.1 U15.31 U510.4
PMD1K_FB_MOT1: C22.2 L6.1 U15.11
PMD1K_FB_MOT2: C1.2 L2.1 U2.11
PMD1K_FB_P2P5V: C680.2 L8.2 R33.1 U15.46
PMD1K_FB_P3P3V: C674.2 L7.2 R32.1 U15.45
PMD1K_FB_P5V: C583.2 L4.1 R19.2 U15.24
PMD1K_GD_CORE: Q2.1 U15.26
PMD1K_GM_IN1: C25.2 R24.2 TP41.1 U15.8
PMD1K_GM_IN2: C511.2 R514.2 TP3.1 U2.8
PMD1K_SENSE_MOT1: R23.1 U15.14
PMD1K_SENSE_MOT2: R5.1 U2.14
PMD1K_VCP: C641.1 U15.21
PMD1K_VREG: C640.1 U15.20 U15.47
PMD_INTZ: R675.2 R676.2 R707.1 U11.AE8 U15.36
POSENSE: R578.2 R579.1 R671.2 R672.2 U15.34
POSENSE_FIL: C551.2 R579.2 U11.P22
PROG_0: R584.1 U7.43 U20.17
PSENS: R671.1 U2.34
PWR_OFF_RDY: U11.B23 U508.9
PWR_ON_AC: J35.1 R618.1
PWR_ON_RDY: U11.C22 U508.6
PWRGOOD: R577.2 R673.2 R674.2 U11.T26 U15.35 U18.4 U513.4
REAL_CWTACH1: R665.2 U15.5
REAL_CWTACH2: R519.2 U2.5
RED_LED_EN: J12.1 RN500.1 U7.63 U519.5
RTCK: J28.11 J32.13 R722.1 R724.1
RTCKR: R722.2 U11.E4
SCI_RXD: R570.1 U7.92
SCI_TXD/PROG_1: RN503.1 U7.4 U20.18
SCL: J2.115 J3.115 J15.2
SCL0: J15.3 J54.1 R627.2 R635.2 U5.6 U11.A10 U16.6 U19.1 U20.23
SCL1: J3.95 J15.1 J55.1 R771.2 U11.D20
SCL2: J56.1 R2.1 R544.2 R545.2 U7.5
SCL2_C: J3.113 R2.2
SCL_VMON: R635.1 U501.9 U510.9 U512.9
SCTRLA_N: J500.6E U11.V1
SCTRLA_P: J500.6D U11.V2
SCTRLB_N: J500.20E U11.J2
SCTRLB_P: J500.20D U11.J1
SDA: J2.117 J3.117 J16.2
SDA0: J16.3 J54.2 R561.2 R636.2 U5.7 U11.B10 U16.5 U19.6 U20.22
SDA1: J3.93 J16.1 J55.2 R770.2 U11.E19
SDA2: J56.2 R10.1 R546.2 R547.2 U7.100
SDA2_C: J3.114 R10.2
SDA_VMON: R636.1 U501.7 U510.7 U512.7
SENSE_PULSE: RN506.1 U7.56 U11.G25 U519.11
SENSE_PULSE_BUF: J23.12 J24.8 J38.12 U519.14
SENSOR_RST: J11.3 RN503.2 U7.51
SEQ_SYNC: R649.2 R650.2 U11.AB9
SP_CLK: J40.3 R45.2
SP_D0: J40.4 R41.2
SP_D1: J40.5 R46.2
SP_D2: J40.6 R42.2
SP_D3: J40.7 R47.2
SP_D4: J40.8 R43.2
SP_D5: J40.9 R44.2
SP_D6: J40.10 R55.2
SP_D7: J40.11 R54.2
SP_FB: J40.12 R56.2
SP_STAT_IN: R593.2 U517.14
SP_WAVE_CLK: U11.G26 U517.2
SP_WAVE_D0: R596.2 U517.3
SP_WAVE_D1: R594.2 U517.4
SP_WAVE_D2: R592.2 U517.5
SP_WAVE_D3: R590.2 U517.6
SP_WAVE_D5: R606.2 U517.8
SSI_3D_TOGGLE: J23.14 J24.15 J38.9 U519.17
SSI_STB_B: J23.8 J24.14 J38.8 J39.4 U519.18
SSI_STB_G: J23.6 J24.12 J38.7 J39.3 U519.19
SSI_STB_R: J23.4 J24.10 J38.6 J39.2 U519.20
SSI_SUBFRAME: J23.21 J24.9 J38.5 U519.21
SSP0_CLK: R28.1 U2.2 U15.2
SSP0_CLK_DMD: J500.10B R27.1
SSP0_CSZ0: R692.1 R693.2 TP52.1 U11.AC5
SSP0_CSZ0_DAD1: J500.12A R693.1
SSP0_CSZ1: R690.2 R691.1 TP45.1 U11.AB6
SSP0_CSZ1_DMD: J500.11C R690.1
SSP0_CSZ2: R667.1 R695.2 TP49.1 U11.AC3
SSP0_CSZ2_PMD1: R695.1 U15.4
SSP0_CSZ3: R694.2 TP42.1 U11.AB4
SSP0_CSZ3_PMD2: R694.1 U2.4
SSP0_CSZ5/SPD6: R57.2 U11.J23 U517.9
SSP0_RXD: J500.11E R35.2 R36.1 R666.2 R668.2 TP54.1 U11.AD5
SSP0_TXD: R30.1 U2.3 U15.3
SSP0_TXD_DMD: J500.10A R29.1
SSP1_CLK: J20.6 R789.2 R796.1 TP34.1 U507.5
SSP1_CSZ0: J20.1 R792.2 R794.1 TP37.1 U507.1
SSP1_DI: J20.4 R790.2 TP36.1 U11.F22 U507.4
SSP1_DO: J20.2 R791.2 R795.1 TP35.1 U507.2
SSP2/LED_DIN: J49.2 RN505.1 TP29.1 U7.50 U11.K24
SSP2_CLK: U11.K23 U518.3
SSP2_CSZ2/SPD7: U11.J24 U517.10
SSP2_CSZ_0: U11.J26 U518.10
SSP2_DO: U11.J25 U518.6
SUBFRAME: RN506.2 U7.64 U11.D22 U519.4
SW_BOOT: C528.1 U505.1
SW_COMP: C542.1 C544.1 U505.6
SW_EN: R573.2 U505.3
SW_PH: C528.2 D501.2 L500.1 U505.8
SW_SS: C541.2 U505.4
SW_VOUT: C543.1 C566.1 L500.2 R575.2 R587.1
SW_VSNS: R520.1 R588.2 U501.14 U505.5
SWNODE2_CORE: D1.1 L1.1 Q1.3 U2.25
SWNODE2_P2P5V: D2.1 L3.1 U2.41
